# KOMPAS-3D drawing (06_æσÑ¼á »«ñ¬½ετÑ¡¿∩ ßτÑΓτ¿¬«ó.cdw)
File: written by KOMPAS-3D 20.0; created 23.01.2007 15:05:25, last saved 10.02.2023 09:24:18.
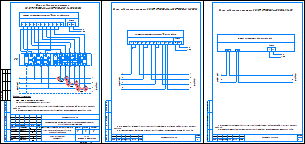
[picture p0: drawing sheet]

Sheets 1-3: A4, portrait

Document properties: Организация: ЗАО ИТФ "СИСТЕМЫ И ТЕХНОЛОГИИ"; Разработал: Антошин; Проверил: Тарасов; Утвердил: Шмончев; Н. контр.: Силаков; Форматы листов документа: 3xA4; Полное имя файла: \\s-tech\depts\Отдел_ПКО\Проекты\Типовые проекты МКД 2023\!Типовой проект\1_Типовой проект МКД_RS-485\06_Схема подключения счетчиков.cdw

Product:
- Part/product: (unnamed)
  - Component: \\Helios\отдел_пко\Общая папка Компас\_Addons\Signatures\Signatures.lfr|Шмончев  | Полное имя файла: C:\Users\MAntoshin\AppData\Local\Temp\hsklda.frw; source file: C:\Program Files\ASCON\KOMPAS-3D V13\Libs\_Addons\Signatures\Signatures.lfr
  - Component: \\Helios\отдел_пко\Общая папка Компас\_Addons\Signatures\Signatures.lfr|Силаков  | Полное имя файла: C:\Users\MAntoshin\AppData\Local\Temp\eiczbt.frw; source file: C:\Program Files\ASCON\KOMPAS-3D V13\Libs\_Addons\Signatures\Signatures.lfr
  - Component: \\Helios\отдел_пко\Общая папка Компас\_Addons\Signatures\Signatures.lfr|Тарасов  | Полное имя файла: C:\Users\MAntoshin\AppData\Local\Temp\qlkzkl.frw; source file: C:\Program Files\ASCON\KOMPAS-3D V13\Libs\_Addons\Signatures\Signatures.lfr

Title block, sheet 1: designation: ВЛСТ 1277.01.003 С5; sheet number: 1; Количество листов документа: 31; organisation: АО ГК / "Системы и Технологии"; Форматы листов документа: A4; stored path: C:\Program Files\ASCON\KOMPAS-3D V8 Plus\Templates\Чертеж строительный зданий и сооружений.cdt; cell 302: Система учета электроэнергии (с организацией удаленного / сбора данных) потребителей; cell 303: Типовой проект ИСУЭ многоквартирного / дома с использованием проводного / канала связи RS-485; cell 304: Схема подключения счетчиков; cell 320: Р
Title block, sheet 2: sheet number: 2; stored path: \\Helios\Отдел_ПКО\Проекты\МРСК Северо-Запада Псковэнерго\Проект\02-07_Рабочая документация\03_Многоквартирный дом,Г.Псков, ул. Труда д. 16а\С5_003_Схема подключения счетчика ЦЭ 2727.cdw
Title block, sheet 3: sheet number: 3; stored path: \\Helios\отдел_пко\Проекты\МРСК Северо-Запада Псковэнерго\Типовой проект\С5_003_Схема подключения счетчика.cdw; designation, second copy: ВЛСТ 1277.01.003 С5-

Referenced files in \\Helios\отдел_пко\Общая папка Компас\_Addons\Signatures\: Signatures.lfr|Тарасов, Signatures.lfr, Signatures.lfr|Силаков, Signatures.lfr|Шмончев
Referenced files in C:\Program Files\ASCON\KOMPAS-3D V13\Libs\_Addons\Signatures\: Signatures.lfr
Referenced files: qlkzkl.frw, eiczbt.frw, hsklda.frw
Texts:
  Тарасов
  Силаков
  Шмончев
  Разраб.
  Н.контр.
  Утв.
  Схема подключения
  счётчиков
  Антошин
  03 Рабочие чертежи основного комплекта. ГОСТ Р 21.1101-2009 Ф3
  05 Чертежи строительных изделий. Посл. листы.  ГОСТ 21.101-97 Ф6
Dimensions and other numbers on the sheet: 1; 31; 02.23; 3; 2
